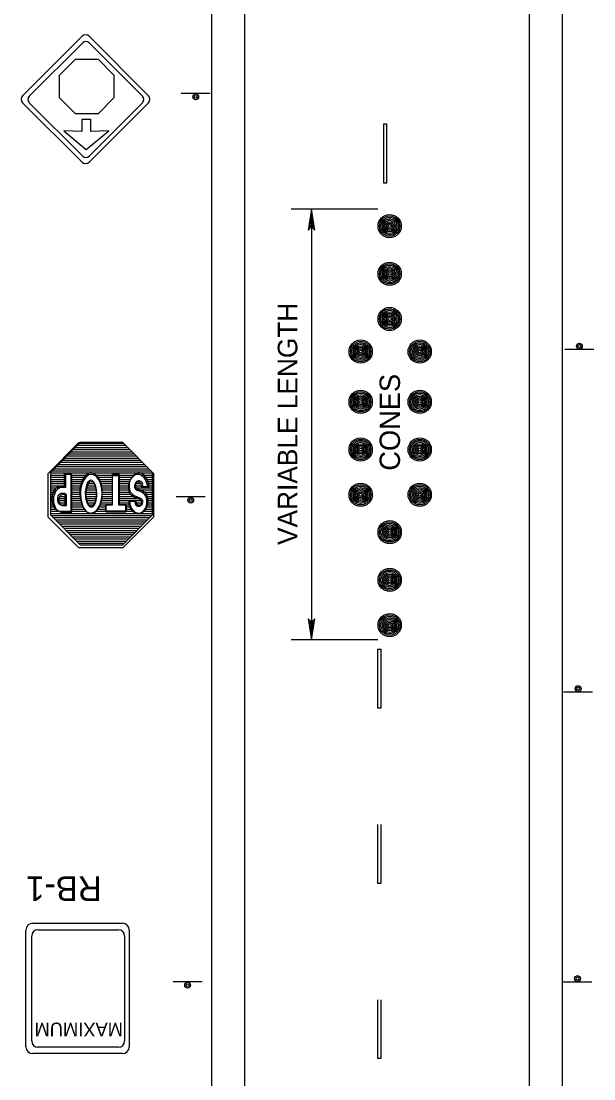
# Model space of a CAD drawing. Extents: x 1361 to 1577, y 123 to 402.
# Drawn here: x 1415.4 to 1462.8, y 206 to 293.6 of the extents above; entities that cross this region are included whole.
import ezdxf

# ---------------------------------------------------------------- set-up
doc = ezdxf.new("R2010")
doc.units = 0
for name, color, linetype in [('Level 1', 7, 'Continuous'), ('Level 10', 7, 'Continuous'), ('Level 2', 7, 'Continuous'), ('Level 44', 7, 'Continuous'), ('Level 60', 7, 'Continuous')]:
    doc.layers.add(name, color=color, linetype=linetype)

msp = doc.modelspace()

# ---------------------------------------------------------------- linework, layer by layer
at = {"layer": 'Level 1'}
for points in [[(1439.427, 278.065), (1439.139, 276.333), (1439.427, 276.621), (1439.716, 276.333), (1439.427, 278.065), (1439.427, 277.534), (1439.271, 276.592), (1439.427, 276.748), (1439.583, 276.592), (1439.427, 277.534), (1439.427, 276.997), (1439.398, 276.835), (1439.427, 276.864), (1439.456, 276.835), (1439.427, 276.997), (1439.427, 276.864)], [(1439.427, 242.409), (1439.716, 244.142), (1439.427, 243.853), (1439.139, 244.142), (1439.427, 242.409), (1439.427, 242.941), (1439.583, 243.882), (1439.427, 243.726), (1439.271, 243.882), (1439.427, 242.941), (1439.427, 243.478), (1439.456, 243.639), (1439.427, 243.61), (1439.398, 243.639), (1439.427, 243.478), (1439.427, 243.61)]]:
    msp.add_lwpolyline(points, dxfattribs=at)
at = {"layer": 'Level 10'}
for p, q in [((1431.161, 386.056), (1431.161, 139.681)), ((1433.872, 386.056), (1433.872, 139.681)), ((1457.451, 386.056), (1457.451, 139.681)), ((1460.18, 386.056), (1460.18, 139.681)), ((1444.916, 278.065), (1437.751, 278.065)), ((1439.427, 278.065), (1439.427, 242.409)), ((1433.872, 265.234), (1433.88, 265.226)), ((1444.916, 242.409), (1437.751, 242.409))]:
    msp.add_line(p, q, dxfattribs=at)
msp.add_lwpolyline([(1421.758, 285.964), (1419.88, 285.964), (1418.555, 287.289), (1418.555, 289.16), (1419.88, 290.486), (1421.758, 290.486), (1423.077, 289.16), (1423.077, 287.289)], close=True, dxfattribs=at)
for centre, radius in [((1445.897, 276.667), 0.962), ((1445.897, 276.667), 0.842), ((1445.897, 276.667), 0.722), ((1445.897, 276.667), 0.602), ((1445.897, 276.667), 0.481), ((1445.897, 276.667), 0.361), ((1445.897, 276.667), 0.241), ((1445.897, 276.667), 0.12), ((1445.897, 272.716), 0.962), ((1445.897, 272.716), 0.842), ((1445.897, 272.716), 0.722), ((1445.897, 272.716), 0.602), ((1445.897, 272.716), 0.481), ((1445.897, 272.716), 0.361), ((1445.897, 272.716), 0.241), ((1445.897, 272.716), 0.12), ((1445.897, 268.972), 0.962), ((1445.897, 268.972), 0.842), ((1445.897, 268.972), 0.722), ((1445.897, 268.972), 0.602), ((1445.897, 268.972), 0.481), ((1445.897, 268.972), 0.361), ((1445.897, 268.972), 0.241), ((1445.897, 268.972), 0.12), ((1443.499, 266.274), 0.962), ((1448.386, 266.274), 0.962), ((1443.499, 266.274), 0.842), ((1443.499, 266.274), 0.722), ((1443.499, 266.274), 0.602), ((1443.499, 266.274), 0.481), ((1443.499, 266.274), 0.361), ((1443.499, 266.274), 0.241), ((1443.499, 266.274), 0.12), ((1448.386, 266.274), 0.842), ((1448.386, 266.274), 0.722), ((1448.386, 266.274), 0.602), ((1448.386, 266.274), 0.481), ((1448.386, 266.274), 0.361), ((1448.386, 266.274), 0.241), ((1448.386, 266.274), 0.12), ((1443.499, 262.114), 0.962), ((1443.499, 262.114), 0.842), ((1443.499, 262.114), 0.722), ((1448.386, 262.114), 0.962), ((1448.386, 262.114), 0.842), ((1448.386, 262.114), 0.722), ((1443.499, 262.114), 0.602), ((1443.499, 262.114), 0.481), ((1443.499, 262.114), 0.361), ((1443.499, 262.114), 0.241), ((1443.499, 262.114), 0.12), ((1448.386, 262.114), 0.602), ((1448.386, 262.114), 0.481), ((1448.386, 262.114), 0.361), ((1448.386, 262.114), 0.241), ((1448.386, 262.114), 0.12), ((1443.499, 258.162), 0.962), ((1443.499, 258.162), 0.842), ((1443.499, 258.162), 0.722), ((1443.499, 258.162), 0.602), ((1443.499, 258.162), 0.481), ((1443.499, 258.162), 0.361), ((1448.386, 258.162), 0.962), ((1448.386, 258.162), 0.842), ((1448.386, 258.162), 0.722), ((1448.386, 258.162), 0.602), ((1448.386, 258.162), 0.481), ((1448.386, 258.162), 0.361), ((1443.499, 258.162), 0.241), ((1443.499, 258.162), 0.12), ((1448.386, 258.162), 0.241), ((1448.386, 258.162), 0.12), ((1443.499, 254.418), 0.962), ((1443.499, 254.418), 0.842), ((1443.499, 254.418), 0.722), ((1443.499, 254.418), 0.602), ((1448.386, 254.418), 0.962), ((1448.386, 254.418), 0.842), ((1448.386, 254.418), 0.722), ((1448.386, 254.418), 0.602), ((1443.499, 254.418), 0.481), ((1443.499, 254.418), 0.361), ((1443.499, 254.418), 0.241), ((1443.499, 254.418), 0.12), ((1448.386, 254.418), 0.481), ((1448.386, 254.418), 0.361), ((1448.386, 254.418), 0.241), ((1448.386, 254.418), 0.12), ((1445.902, 251.319), 0.962), ((1445.902, 251.319), 0.842), ((1445.902, 251.319), 0.722), ((1445.902, 251.319), 0.602), ((1445.902, 251.319), 0.481), ((1445.902, 251.319), 0.361), ((1445.902, 251.319), 0.241), ((1445.902, 251.319), 0.12), ((1445.902, 247.368), 0.962), ((1445.902, 247.368), 0.842), ((1445.902, 247.368), 0.722), ((1445.902, 247.368), 0.602), ((1445.902, 247.368), 0.481), ((1445.902, 247.368), 0.361), ((1445.902, 247.368), 0.241), ((1445.902, 247.368), 0.12), ((1445.902, 243.623), 0.962), ((1445.902, 243.623), 0.842), ((1445.902, 243.623), 0.722), ((1445.902, 243.623), 0.602), ((1445.902, 243.623), 0.481), ((1445.902, 243.623), 0.361), ((1445.902, 243.623), 0.241), ((1445.902, 243.623), 0.12)]:
    msp.add_circle(centre, radius, dxfattribs=at)
at = {"layer": 'Level 2'}
for p, q in [((1445.38, 285.098), (1445.38, 280.26)), ((1445.67, 285.098), (1445.38, 285.098)), ((1445.67, 280.26), (1445.67, 285.098)), ((1445.38, 280.26), (1445.67, 280.26)), ((1444.897, 241.614), (1444.897, 236.776)), ((1445.187, 241.614), (1444.897, 241.614)), ((1445.187, 236.776), (1445.187, 241.614)), ((1444.897, 236.776), (1445.187, 236.776)), ((1444.897, 227.1), (1444.897, 222.262)), ((1445.187, 222.262), (1445.187, 227.1)), ((1444.897, 222.262), (1445.187, 222.262)), ((1444.897, 212.586), (1444.897, 207.748)), ((1445.187, 207.748), (1445.187, 212.586)), ((1444.897, 207.748), (1445.187, 207.748))]:
    msp.add_line(p, q, dxfattribs=at)
at = {"layer": 'Level 44'}
for p, q in [((1420.431, 292.388), (1415.516, 287.468)), ((1416.066, 287.415), (1420.49, 291.841)), ((1425.934, 287.468), (1421.012, 292.388)), ((1421.012, 291.841), (1425.442, 287.415)), ((1425.931, 287.468), (1425.934, 287.468)), ((1431.052, 287.646), (1428.646, 287.646)), ((1415.516, 286.884), (1420.431, 281.97)), ((1420.49, 282.465), (1416.066, 286.888)), ((1425.442, 286.888), (1421.012, 282.465)), ((1421.012, 281.97), (1425.934, 286.884)), ((1426.227, 287.173), (1426.227, 287.173)), ((1420.406, 285.482), (1420.406, 284.489)), ((1421.152, 285.482), (1420.411, 285.482)), ((1421.152, 284.489), (1421.152, 285.482)), ((1420.406, 284.489), (1418.919, 284.569)), ((1418.919, 284.569), (1420.778, 283.001)), ((1420.778, 283.001), (1422.639, 284.569)), ((1422.639, 284.569), (1421.152, 284.489)), ((1460.394, 266.461), (1462.8, 266.461)), ((1420.284, 258.737), (1417.81, 256.265)), ((1423.806, 258.737), (1420.284, 258.737)), ((1426.279, 256.265), (1423.806, 258.737)), ((1417.81, 256.265), (1417.81, 252.742)), ((1418.974, 255.123), (1418.974, 256.211)), ((1418.974, 256.211), (1419.504, 256.211)), ((1419.586, 256.081), (1419.072, 256.081)), ((1419.072, 256.081), (1419.072, 255.024)), ((1419.504, 256.211), (1419.504, 253.018)), ((1419.586, 252.981), (1419.586, 256.081)), ((1423.475, 255.99), (1422.939, 255.99)), ((1422.939, 255.99), (1422.939, 253.567)), ((1422.958, 256.117), (1423.51, 256.117)), ((1422.958, 253.62), (1422.958, 256.117)), ((1423.475, 253.552), (1423.475, 255.99)), ((1423.51, 256.117), (1423.51, 253.606)), ((1426.279, 252.742), (1426.279, 256.265)), ((1418.974, 255.123), (1418.64, 255.123)), ((1418.656, 255.115), (1418.974, 255.123)), ((1419.072, 255.024), (1418.747, 255.024)), ((1425.87, 254.989), (1425.384, 254.989)), ((1425.977, 255.086), (1425.477, 255.086)), ((1425.818, 255.718), (1425.821, 255.716)), ((1419.038, 254.52), (1418.698, 254.52)), ((1419.038, 254.52), (1418.698, 254.52)), ((1419.136, 254.44), (1418.804, 254.44)), ((1419.136, 254.44), (1418.804, 254.44)), ((1419.038, 253.591), (1419.038, 254.52)), ((1419.038, 253.591), (1419.038, 254.52)), ((1419.136, 253.538), (1419.136, 254.44)), ((1419.136, 253.538), (1419.136, 254.44)), ((1430.636, 254.244), (1428.23, 254.244)), ((1418.691, 253.591), (1419.038, 253.591)), ((1418.691, 253.591), (1419.038, 253.591)), ((1418.797, 253.538), (1419.136, 253.538)), ((1418.797, 253.538), (1419.136, 253.538)), ((1421.223, 253.449), (1421.2, 253.445)), ((1422.939, 253.567), (1422.397, 253.567)), ((1422.397, 253.567), (1422.397, 253.01)), ((1422.399, 253.047), (1422.399, 253.62)), ((1422.399, 253.62), (1422.958, 253.62)), ((1424.046, 253.552), (1423.475, 253.552)), ((1423.51, 253.606), (1424.098, 253.606)), ((1424.046, 253.01), (1424.046, 253.552)), ((1424.098, 253.606), (1424.098, 253.047)), ((1424.299, 253.876), (1424.828, 253.876)), ((1424.359, 253.94), (1424.904, 253.94)), ((1417.81, 252.742), (1420.284, 250.269)), ((1419.504, 253.018), (1418.61, 253.018)), ((1418.719, 252.981), (1419.586, 252.981)), ((1421.201, 252.906), (1421.185, 252.905)), ((1422.397, 253.01), (1424.046, 253.01)), ((1424.098, 253.047), (1422.399, 253.047)), ((1423.806, 250.269), (1426.279, 252.742)), ((1420.284, 250.269), (1423.806, 250.269)), ((1426.279, 250.269), (1426.279, 250.269)), ((1460.29, 238.092), (1462.696, 238.092)), ((1415.792, 208.703), (1415.792, 218.359)), ((1416.365, 218.934), (1423.772, 218.934)), ((1416.78, 218.386), (1423.448, 218.386)), ((1423.641, 218.696), (1423.641, 218.696)), ((1424.344, 218.363), (1424.344, 218.359)), ((1424.344, 218.359), (1424.344, 208.703)), ((1416.265, 209.179), (1416.265, 217.871)), ((1423.962, 217.873), (1423.962, 217.871)), ((1423.962, 217.871), (1423.962, 209.179)), ((1430.383, 214.069), (1427.977, 214.069)), ((1460.239, 214.069), (1462.645, 214.069)), ((1423.448, 208.665), (1416.78, 208.665)), ((1423.772, 208.131), (1416.365, 208.131))]:
    msp.add_line(p, q, dxfattribs=at)
msp.add_lwpolyline([(1417.629, 256.189), (1420.177, 258.737), (1423.806, 258.737), (1426.354, 256.189), (1426.354, 252.56), (1423.806, 250.012), (1420.177, 250.012), (1417.629, 252.56)], close=True, dxfattribs=at)
for points in [[(1424.053, 258.484), (1420.031, 258.484)], [(1423.884, 258.66), (1420.206, 258.66)], [(1424.94, 257.603), (1419.149, 257.603)], [(1424.765, 257.779), (1419.326, 257.779)], [(1424.588, 257.956), (1419.502, 257.956)], [(1424.412, 258.132), (1419.678, 258.132)], [(1424.236, 258.308), (1419.854, 258.308)], [(1425.821, 256.723), (1418.269, 256.723)], [(1425.645, 256.898), (1418.445, 256.898)], [(1425.469, 257.075), (1418.622, 257.075)], [(1425.293, 257.251), (1418.797, 257.251)], [(1425.117, 257.427), (1418.973, 257.427)], [(1426.279, 256.194), (1417.81, 256.194)], [(1419.072, 256.018), (1417.81, 256.018)], [(1419.072, 255.842), (1417.81, 255.842)], [(1426.174, 256.37), (1417.917, 256.37)], [(1425.997, 256.547), (1418.093, 256.547)], [(1420.939, 256.018), (1419.586, 256.018)], [(1420.727, 255.842), (1419.586, 255.842)], [(1424.785, 256.018), (1421.495, 256.018)], [(1422.939, 255.842), (1421.706, 255.842)], [(1424.553, 255.842), (1423.475, 255.842)], [(1426.279, 256.018), (1425.328, 256.018)], [(1426.279, 255.842), (1425.533, 255.842)], [(1419.072, 255.666), (1417.81, 255.666)], [(1419.072, 255.489), (1417.81, 255.489)], [(1419.072, 255.314), (1417.81, 255.314)], [(1419.072, 255.138), (1417.81, 255.138)], [(1418.558, 254.961), (1417.81, 254.961)], [(1420.601, 255.666), (1419.586, 255.666)], [(1420.509, 255.489), (1419.586, 255.489)], [(1420.439, 255.314), (1419.586, 255.314)], [(1420.39, 255.138), (1419.586, 255.138)], [(1420.354, 254.961), (1419.586, 254.961)], [(1421.608, 254.961), (1420.805, 254.961)], [(1421.552, 255.138), (1420.854, 255.138)], [(1421.475, 255.314), (1420.946, 255.314)], [(1422.939, 255.666), (1421.833, 255.666)], [(1422.939, 255.489), (1421.925, 255.489)], [(1422.939, 255.314), (1421.989, 255.314)], [(1422.939, 255.138), (1422.038, 255.138)], [(1422.939, 254.961), (1422.066, 254.961)], [(1424.426, 255.666), (1423.475, 255.666)], [(1424.342, 255.489), (1423.475, 255.489)], [(1424.285, 255.314), (1423.475, 255.314)], [(1424.271, 255.138), (1423.475, 255.138)], [(1424.271, 254.961), (1423.475, 254.961)], [(1425.37, 255.138), (1424.772, 255.138)], [(1426.279, 254.961), (1424.792, 254.961)], [(1425.314, 255.314), (1424.813, 255.314)], [(1426.279, 255.666), (1425.674, 255.666)], [(1426.279, 255.489), (1425.758, 255.489)], [(1426.279, 255.314), (1425.815, 255.314)], [(1426.279, 255.138), (1425.849, 255.138)], [(1418.318, 254.785), (1417.81, 254.785)], [(1418.199, 254.609), (1417.81, 254.609)], [(1418.135, 254.433), (1417.81, 254.433)], [(1418.086, 254.257), (1417.81, 254.257)], [(1418.064, 254.08), (1417.81, 254.08)], [(1419.142, 254.08), (1418.508, 254.08)], [(1419.136, 254.257), (1418.565, 254.257)], [(1420.326, 254.785), (1419.586, 254.785)], [(1420.312, 254.609), (1419.586, 254.609)], [(1420.305, 254.433), (1419.586, 254.433)], [(1420.319, 254.257), (1419.586, 254.257)], [(1420.333, 254.08), (1419.586, 254.08)], [(1421.665, 254.609), (1420.749, 254.609)], [(1421.665, 254.433), (1420.756, 254.433)], [(1421.651, 254.257), (1420.756, 254.257)], [(1421.644, 254.785), (1420.77, 254.785)], [(1421.644, 254.08), (1420.784, 254.08)], [(1422.939, 254.08), (1422.073, 254.08)], [(1422.939, 254.785), (1422.087, 254.785)], [(1422.933, 254.257), (1422.094, 254.257)], [(1422.939, 254.609), (1422.101, 254.609)], [(1422.939, 254.433), (1422.101, 254.433)], [(1424.299, 254.785), (1423.475, 254.785)], [(1424.349, 254.609), (1423.475, 254.609)], [(1424.483, 254.433), (1423.475, 254.433)], [(1424.722, 254.257), (1423.475, 254.257)], [(1425.117, 254.08), (1423.475, 254.08)], [(1426.279, 254.785), (1424.976, 254.785)], [(1426.279, 254.609), (1425.392, 254.609)], [(1426.279, 254.433), (1425.617, 254.433)], [(1426.279, 254.257), (1425.729, 254.257)], [(1426.279, 254.08), (1425.779, 254.08)], [(1418.072, 253.905), (1417.81, 253.905)], [(1418.093, 253.728), (1417.81, 253.728)], [(1418.135, 253.552), (1417.81, 253.552)], [(1418.22, 253.376), (1417.81, 253.376)], [(1418.332, 253.2), (1417.81, 253.2)], [(1419.136, 253.905), (1418.515, 253.905)], [(1419.136, 253.728), (1418.558, 253.728)], [(1419.136, 253.552), (1418.727, 253.552)], [(1420.368, 253.905), (1419.586, 253.905)], [(1420.411, 253.728), (1419.586, 253.728)], [(1420.474, 253.552), (1419.586, 253.552)], [(1420.551, 253.376), (1419.586, 253.376)], [(1420.664, 253.2), (1419.586, 253.2)], [(1421.594, 253.905), (1420.826, 253.905)], [(1421.545, 253.728), (1420.883, 253.728)], [(1421.46, 253.552), (1420.967, 253.552)], [(1422.397, 253.2), (1421.742, 253.2)], [(1422.397, 253.376), (1421.862, 253.376)], [(1422.397, 253.552), (1421.939, 253.552)], [(1422.939, 253.728), (1422.003, 253.728)], [(1422.939, 253.905), (1422.045, 253.905)], [(1425.342, 253.905), (1423.475, 253.905)], [(1424.307, 253.728), (1423.475, 253.728)], [(1424.349, 253.552), (1424.046, 253.552)], [(1424.398, 253.376), (1424.046, 253.376)], [(1424.497, 253.2), (1424.046, 253.2)], [(1425.37, 253.728), (1424.821, 253.728)], [(1425.293, 253.552), (1424.899, 253.552)], [(1426.279, 253.2), (1425.61, 253.2)], [(1426.279, 253.376), (1425.709, 253.376)], [(1426.279, 253.552), (1425.758, 253.552)], [(1426.279, 253.728), (1425.792, 253.728)], [(1426.279, 253.905), (1425.8, 253.905)], [(1418.558, 253.024), (1417.81, 253.024)], [(1426.279, 252.848), (1417.81, 252.848)], [(1426.209, 252.671), (1417.881, 252.671)], [(1426.033, 252.496), (1418.058, 252.496)], [(1425.856, 252.319), (1418.233, 252.319)], [(1420.833, 253.024), (1419.586, 253.024)], [(1422.397, 253.024), (1421.581, 253.024)], [(1424.652, 253.024), (1424.046, 253.024)], [(1426.279, 253.024), (1425.462, 253.024)], [(1425.68, 252.143), (1418.41, 252.143)], [(1425.504, 251.967), (1418.586, 251.967)], [(1425.328, 251.791), (1418.762, 251.791)], [(1425.152, 251.615), (1418.938, 251.615)], [(1424.976, 251.439), (1419.114, 251.439)], [(1424.8, 251.263), (1419.29, 251.263)], [(1424.624, 251.086), (1419.474, 251.086)], [(1424.447, 250.91), (1419.643, 250.91)], [(1424.271, 250.734), (1419.819, 250.734)], [(1424.095, 250.558), (1420.002, 250.558)], [(1423.919, 250.382), (1420.171, 250.382)]]:
    msp.add_lwpolyline(points, dxfattribs=at)
for centre, radius in [((1429.844, 287.376), 0.241), ((1429.844, 287.376), 0.12), ((1461.601, 266.73), 0.241), ((1461.601, 266.73), 0.12), ((1429.428, 253.974), 0.241), ((1429.428, 253.974), 0.12), ((1461.498, 238.361), 0.241), ((1461.498, 238.361), 0.12), ((1429.175, 213.799), 0.241), ((1429.175, 213.799), 0.12), ((1461.447, 214.339), 0.241), ((1461.447, 214.339), 0.12)]:
    msp.add_circle(centre, radius, dxfattribs=at)
for centre, radius, start, end in [((1420.723, 292.094), 0.412, 45, 135), ((1420.752, 291.578), 0.37, 45, 135), ((1415.806, 287.177), 0.412, 135, 225), ((1416.327, 287.152), 0.37, 135, 225), ((1425.178, 287.152), 0.37, 315, 44.99999), ((1425.64, 287.177), 0.412, 315, 44.99999), ((1420.752, 282.727), 0.37, 225, 315), ((1420.723, 282.26), 0.412, 225, 315), ((1425.805, 255.028), 1.512, 145.50918, 163.2894), ((1425.184, 255.281), 0.843, 113.14132, 144.99055), ((1425.27, 255.387), 0.868, 113.14132, 144.99056), ((1425.06, 255.567), 0.528, 52.05359, 112.73967), ((1425.142, 255.681), 0.544, 52.05359, 112.73967), ((1424.7, 255.053), 1.154, 28.41537, 53.6553), ((1424.772, 255.152), 1.189, 28.41538, 53.65531), ((1418.623, 254.556), 0.531, 115.38384, 142.61875), ((1418.731, 254.475), 0.515, 115.38384, 142.61875), ((1418.781, 254.353), 0.784, 106.60198, 119.80906), ((1418.885, 254.278), 0.761, 106.60197, 119.80905), ((1418.623, 254.933), 0.184, 79.79086, 113.54187), ((1418.732, 254.841), 0.179, 79.79086, 113.54186), ((1426.141, 255.063), 1.867, 171.24702, 183.9864), ((1425.59, 255.067), 1.319, 185.90969, 201.98649), ((1425.703, 254.933), 1.468, 145.50918, 163.2894), ((1426.256, 255.162), 1.924, 171.24702, 183.9864), ((1425.688, 255.166), 1.359, 185.90969, 201.9865), ((1425.117, 255.093), 0.344, 172.57608, 210.47755), ((1425.22, 255.134), 0.445, 146.25303, 178.73226), ((1425.128, 255.133), 0.375, 214.20826, 254.15525), ((1425.075, 255.131), 0.335, 95.43739, 134.06254), ((1425.201, 255.193), 0.355, 172.57609, 210.47756), ((1425.308, 255.235), 0.459, 146.25303, 178.73226), ((1425.212, 255.234), 0.387, 214.20826, 254.15525), ((1425.158, 255.232), 0.345, 95.4374, 134.06255), ((1425.048, 255.103), 0.361, 50.6966, 91.45727), ((1425.13, 255.203), 0.372, 50.6966, 91.45728), ((1424.999, 255.136), 0.371, 6.87276, 42.74491), ((1425.079, 255.238), 0.382, 6.87276, 42.74491), ((1424.651, 254.997), 0.739, 359.01714, 13.5172), ((1424.721, 255.094), 0.761, 359.01715, 13.51721), ((1424.25, 254.917), 1.62, 2.38408, 24.95187), ((1424.308, 255.012), 1.669, 2.38409, 24.95188), ((1419.283, 254.077), 1.35, 169.75207, 182.79164), ((1419.283, 254.077), 1.35, 169.75207, 182.79164), ((1419.684, 253.972), 1.764, 158.31533, 168.66985), ((1418.846, 254.31), 0.86, 138.29225, 158.60313), ((1418.846, 254.31), 0.86, 138.29225, 158.60313), ((1419.372, 254.01), 1.31, 169.75207, 182.79164), ((1419.372, 254.01), 1.31, 169.75207, 182.79164), ((1419.762, 253.908), 1.712, 158.31533, 168.66985), ((1418.948, 254.235), 0.835, 138.29224, 158.60313), ((1418.948, 254.235), 0.835, 138.29225, 158.60313), ((1418.909, 254.05), 0.52, 170.34165, 195.23421), ((1418.909, 254.05), 0.52, 170.34165, 195.23421), ((1418.86, 254.113), 0.464, 146.50855, 177.0313), ((1418.86, 254.113), 0.464, 146.50855, 177.0313), ((1418.771, 254.166), 0.361, 101.91914, 145.7868), ((1418.771, 254.166), 0.361, 101.91914, 145.7868), ((1419.009, 253.983), 0.504, 170.34164, 195.2342), ((1419.009, 253.983), 0.504, 170.34164, 195.2342), ((1418.962, 254.045), 0.45, 146.50855, 177.03129), ((1418.962, 254.045), 0.45, 146.50855, 177.03129), ((1418.876, 254.096), 0.35, 101.91913, 145.78679), ((1418.876, 254.096), 0.35, 101.91913, 145.78679), ((1422.771, 253.032), 2.214, 39.47896, 43.42604), ((1422.784, 253.07), 2.281, 39.47897, 43.42605), ((1425.361, 255.35), 1.267, 226.24648, 247.92633), ((1425.453, 255.458), 1.305, 226.24648, 247.92633), ((1424.297, 252.462), 1.811, 57.98164, 70.97904), ((1424.357, 252.483), 1.866, 57.98164, 70.97904), ((1422.88, 249.217), 5.955, 64.46241, 68.83121), ((1422.897, 249.14), 6.134, 64.46241, 68.83121), ((1425.205, 253.837), 0.268, 344.13099, 58.14758), ((1424.986, 253.911), 0.822, 20.44809, 55.11069), ((1425.066, 253.975), 0.847, 20.4481, 55.11069), ((1424.646, 253.877), 1.155, 354.81714, 15.91833), ((1424.716, 253.94), 1.19, 354.81715, 15.91834), ((1419.611, 254.11), 1.68, 183.39027, 195.65974), ((1418.835, 253.855), 0.864, 193.06738, 213.76202), ((1419.691, 254.042), 1.63, 183.39027, 195.65974), ((1418.824, 253.776), 0.814, 209.22414, 228.53082), ((1418.824, 253.776), 0.814, 209.22414, 228.53082), ((1418.938, 253.794), 0.839, 193.06737, 213.76201), ((1418.927, 253.717), 0.79, 209.22414, 228.53081), ((1418.927, 253.717), 0.79, 209.22414, 228.53081), ((1418.658, 253.543), 0.53, 224.85284, 265.0441), ((1418.891, 253.987), 0.489, 188.60306, 214.21696), ((1418.891, 253.987), 0.489, 188.60306, 214.21696), ((1418.744, 253.893), 0.315, 215.11978, 259.31166), ((1418.744, 253.893), 0.315, 215.11978, 259.31166), ((1418.992, 253.922), 0.475, 188.60306, 214.21695), ((1418.992, 253.922), 0.475, 188.60306, 214.21695), ((1418.85, 253.831), 0.306, 215.11978, 259.31166), ((1418.85, 253.831), 0.306, 215.11978, 259.31166), ((1425.643, 253.9), 1.341, 180.69517, 197.14514), ((1425.743, 253.964), 1.381, 180.69518, 197.14515), ((1425.299, 253.747), 0.968, 194.56402, 229.0063), ((1425.389, 253.806), 0.998, 194.56402, 229.00631), ((1425.249, 253.811), 0.436, 170.44121, 219.3244), ((1425.337, 253.872), 0.449, 170.44122, 219.32441), ((1425.109, 253.759), 0.298, 227.30173, 289.01193), ((1425.193, 253.818), 0.308, 227.30173, 289.01194), ((1425.087, 253.736), 0.285, 293.8064, 352.24074), ((1425.12, 253.777), 0.261, 344.13098, 58.14757), ((1425.17, 253.795), 0.294, 293.8064, 352.24074), ((1424.844, 253.727), 0.939, 303.36619, 335.67343), ((1424.92, 253.786), 0.967, 303.3662, 335.67344), ((1424.484, 253.84), 1.315, 337.73321, 357.13918), ((1424.549, 253.903), 1.355, 337.73321, 357.13918), ((1418.766, 253.491), 0.515, 224.85284, 265.0441), ((1425.06, 253.432), 0.574, 226.13685, 301.39871), ((1425.142, 253.482), 0.591, 226.13686, 301.39871), ((1416.364, 218.362), 0.572, 90, 179.99999), ((1416.781, 217.873), 0.514, 90, 179.99999), ((1423.448, 217.873), 0.514, 360, 89.99999), ((1423.772, 218.362), 0.572, 360, 89.99999), ((1416.364, 208.704), 0.572, 179.99999, 269.99999), ((1416.781, 209.181), 0.514, 179.99999, 269.99999), ((1423.448, 209.181), 0.514, 270, 359.99999), ((1423.772, 208.704), 0.572, 270, 359.99999)]:
    msp.add_arc(centre, radius, start, end, dxfattribs=at)
for centre, major_axis, ratio, start_param, end_param in [((1421.172, 254.568), (0.011, 1.663), 0.558644, 0.656861, 3.168126), ((1421.206, 254.486), (0.011, 1.614), 0.558644, 3.185857, 9.451311), ((1421.172, 254.568), (0.011, 1.663), 0.558644, 4.129576, 6.939747), ((1421.172, 254.53), (-0.006, 1.086), 0.432619, 0.881967, 3.190734), ((1421.206, 254.449), (-0.005, 1.054), 0.432619, 3.239639, 9.473919), ((1421.172, 254.53), (-0.006, 1.086), 0.432619, 3.890436, 7.165085), ((1421.172, 254.568), (0.011, 1.663), 0.558644, 3.185857, 4.129398), ((1421.172, 254.53), (-0.006, 1.086), 0.432619, 3.239639, 3.888884)]:
    msp.add_ellipse(centre, major_axis=major_axis, ratio=ratio, start_param=start_param, end_param=end_param, dxfattribs=at)

# ---------------------------------------------------------------- texts
at = {"layer": 'Level 10'}
for s, height, rotation, p in [('CONES', 1.6865, 89.99999, (1446.753, 256.408)), ('RB-1', 2.0571, 180, (1422.071, 222.817))]:
    msp.add_text(s, height=height, rotation=rotation, dxfattribs=at).set_placement(p)
at = {"layer": 'Level 44'}
msp.add_text('MAXIMUM', height=1.1333, rotation=180, dxfattribs=at).set_placement((1423.823, 210.699))
at = {"layer": 'Level 60'}
msp.add_text('VARIABLE LENGTH', height=1.62645, rotation=90, dxfattribs=at).set_placement((1438.26, 250.259))

doc.saveas('drawing.dxf')
